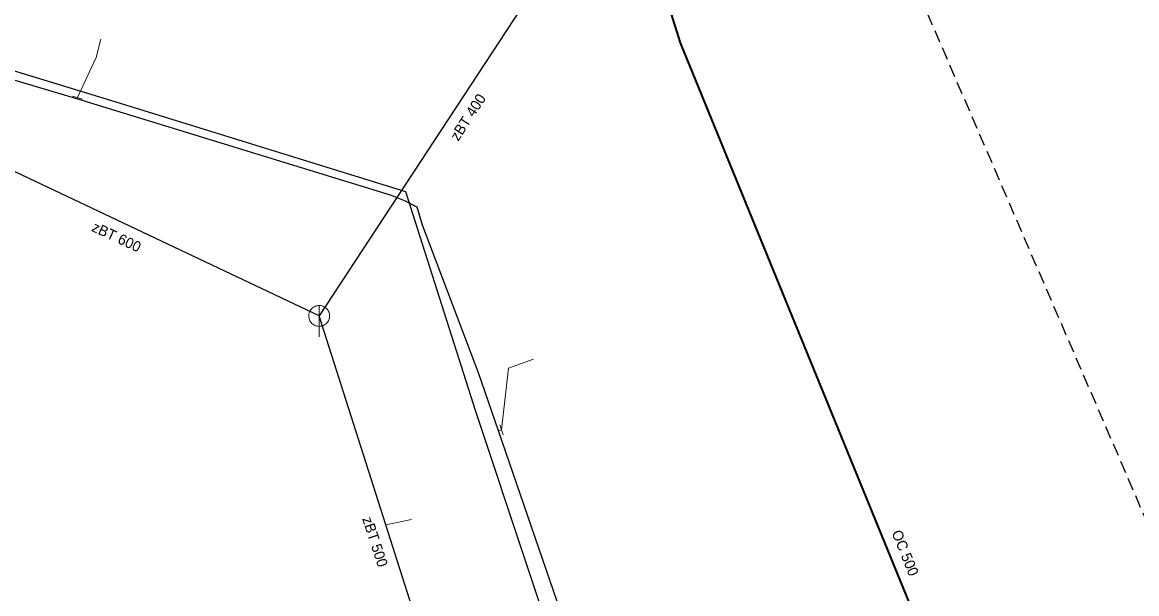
# Model space of a CAD drawing. Extents: x -774415 to -774100, y -975744 to -975502.
# Drawn here: x -774263.4 to -774156.5, y -975611.6 to -975556.8 of the extents above; entities that cross this region are included whole.
import ezdxf

# ---------------------------------------------------------------- set-up
doc = ezdxf.new("R2010")
doc.units = 0
doc.header["$LTSCALE"] = 0.4
doc.linetypes.add('MEDIUM_DASHED', pattern=[4.5, 3, -1.5])
for name, color, linetype, lineweight in [('1', 7, 'MEDIUM_DASHED', 25), ('11', 7, 'Continuous', 13), ('13', 7, 'Continuous', 13), ('14', 7, 'Continuous', 13), ('17', 7, 'Continuous', 25), ('22', 7, 'Continuous', 13), ('34', 7, 'Continuous', 13)]:
    doc.layers.add(name, color=color, linetype=linetype, lineweight=lineweight)

msp = doc.modelspace()

# ---------------------------------------------------------------- linework, layer by layer
at = {"layer": '1'}
msp.add_lwpolyline([(-774414.714, -975561.823), (-774378.138, -975501.935), (-774197.267, -975507.964), (-774100.401, -975732.645), (-774205.708, -975744.301), (-774260.773, -975651.856)], close=True, dxfattribs=at)
at = {"layer": '11'}
msp.add_line((-774228.52, -975605.003), (-774226.057, -975604.476), dxfattribs=at)
at = {"layer": '13'}
for points in [[(-774258.081, -975563.998), (-774256.291, -975560.135), (-774255.835, -975558.381)], [(-774217.43, -975595.879), (-774216.745, -975589.96), (-774214.375, -975589.081)]]:
    msp.add_lwpolyline(points, dxfattribs=at)
at = {"layer": '14', "lineweight": 25}
for p, q in [((-774207.729, -975543.497), (-774234.913, -975584.951)), ((-774234.913, -975584.951), (-774270.686, -975567.987))]:
    msp.add_line(p, q, dxfattribs=at)
at = {"layer": '14'}
for p, q in [((-774258.14, -975564.129), (-774258.081, -975563.998)), ((-774217.71, -975595.969), (-774217.43, -975595.879))]:
    msp.add_line(p, q, dxfattribs=at)
at = {"layer": '14', "lineweight": 25}
msp.add_lwpolyline([(-774220.768, -975629.317), (-774228.52, -975605.003), (-774234.913, -975584.951)], dxfattribs=at)
at = {"layer": '17', "lineweight": 35}
msp.add_lwpolyline([(-774217.009, -975507.306), (-774211.739, -975524.879), (-774208.02, -975534.129), (-774200.302, -975558.73), (-774159.333, -975659.052), (-774159.853, -975667.971), (-774158.147, -975697.895), (-774164.627, -975739.754)], dxfattribs=at)
at = {"layer": '17'}
for points in [[(-774190.98, -975675.3), (-774195.739, -975661.53), (-774202.46, -975642.109), (-774207.43, -975626.379), (-774211.07, -975615.34), (-774217.71, -975595.969), (-774219.62, -975590.41), (-774224.989, -975576.25), (-774225.51, -975574.5), (-774226.62, -975573.949), (-774228.079, -975573.359), (-774258.14, -975564.129), (-774273.649, -975559.52), (-774289.02, -975554.649), (-774309.699, -975548.23), (-774320.17, -975544.98), (-774321.69, -975541.59), (-774344.199, -975534.469), (-774360.363, -975529.358), (-774373.359, -975525.199), (-774377.583, -975527.43), (-774378.039, -975527.68), (-774378.399, -975527.859), (-774381.76, -975529.64)], [(-774273.912, -975558.461), (-774254.809, -975564.278), (-774226.618, -975573.011), (-774219.919, -975594.089), (-774205.166, -975638.503)]]:
    msp.add_lwpolyline(points, dxfattribs=at)
at = {"layer": '22'}
msp.add_line((-774234.913, -975586.951), (-774234.912, -975583.951), dxfattribs=at)
msp.add_lwpolyline([(-774233.913, -975584.951), (-774233.918, -975584.842), (-774233.936, -975584.734), (-774233.966, -975584.628), (-774234.006, -975584.527), (-774234.058, -975584.43), (-774234.12, -975584.34), (-774234.192, -975584.257), (-774234.272, -975584.183), (-774234.36, -975584.117), (-774234.454, -975584.062), (-774234.554, -975584.017), (-774234.659, -975583.984), (-774234.766, -975583.962), (-774234.875, -975583.952), (-774234.985, -975583.954), (-774235.093, -975583.968), (-774235.2, -975583.993), (-774235.303, -975584.03), (-774235.401, -975584.079), (-774235.493, -975584.137), (-774235.579, -975584.206), (-774235.656, -975584.283), (-774235.725, -975584.369), (-774235.784, -975584.461), (-774235.832, -975584.559), (-774235.869, -975584.662), (-774235.895, -975584.769), (-774235.909, -975584.877), (-774235.912, -975584.987), (-774235.902, -975585.096), (-774235.881, -975585.203), (-774235.847, -975585.307), (-774235.803, -975585.407), (-774235.748, -975585.502), (-774235.682, -975585.59), (-774235.608, -975585.67), (-774235.525, -975585.742), (-774235.435, -975585.804), (-774235.339, -975585.856), (-774235.237, -975585.897), (-774235.132, -975585.927), (-774235.024, -975585.945), (-774234.914, -975585.951), (-774234.805, -975585.945), (-774234.697, -975585.927), (-774234.592, -975585.898), (-774234.49, -975585.857), (-774234.393, -975585.805), (-774234.303, -975585.743), (-774234.22, -975585.672), (-774234.145, -975585.592), (-774234.08, -975585.504), (-774234.024, -975585.41), (-774233.98, -975585.31), (-774233.946, -975585.206), (-774233.924, -975585.098), (-774233.914, -975584.989)], close=True, dxfattribs=at)
at = {"layer": '34'}
for p, q in [((-774258.561, -975563.859), (-774257.6, -975564.137)), ((-774217.583, -975595.403), (-774217.277, -975596.355))]:
    msp.add_line(p, q, dxfattribs=at)

# ---------------------------------------------------------------- texts
at = {"layer": '1'}
for s, rotation, p in [('zBT 400 ', 57, (-774221.579, -975568.239)), ('zBT 600 ', 335, (-774256.811, -975576.763)), ('zBT 500 ', 288, (-774230.794, -975604.402)), ('OC 500', 292, (-774180.039, -975605.74))]:
    msp.add_text(s, height=1, rotation=rotation, dxfattribs=at).set_placement(p)

doc.saveas('drawing.dxf')
